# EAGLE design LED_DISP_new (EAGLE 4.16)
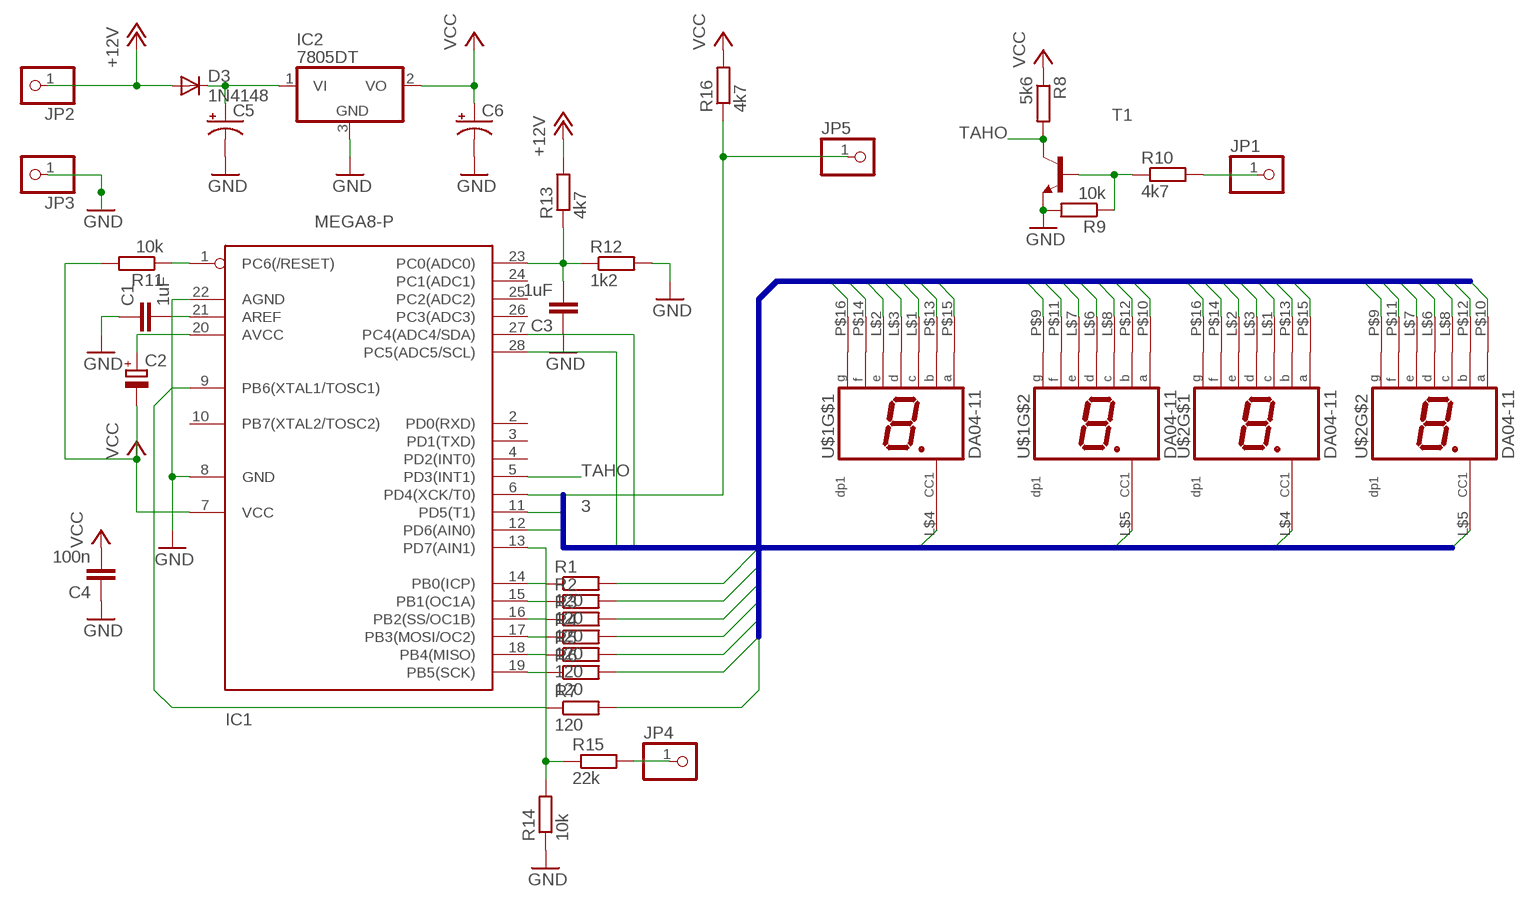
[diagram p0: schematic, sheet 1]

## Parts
C1  1uF  C-EUC1206  [C1206]
C2  CPOL-EUE2,5-6E  [E2,5-6E]
C3  1uF  C-EUC1206  [C1206]
C4  100n  C-EUC1206  [C1206]
C5  CPOL-USSANYO_C6  [SANYO-OSCON_C6]
C6  CPOL-USSANYO_C6  [SANYO-OSCON_C6]
D3  1N4148  [DO35-10]
IC1  MEGA8-P  [DIL28-3]
IC2  7805DT  [TO252]
JP1  PINHD-1X1  [1X01]
JP2  PINHD-1X1  [1X01]
JP3  PINHD-1X1  [1X01]
JP4  PINHD-1X1  [1X01]
JP5  PINHD-1X1  [1X01]
R1  120  R-EU_R1206  [R1206]
R2  120  R-EU_R1206  [R1206]
R3  120  R-EU_R1206  [R1206]
R4  120  R-EU_R1206  [R1206]
R5  120  R-EU_R1206  [R1206]
R6  120  R-EU_R1206  [R1206]
R7  120  R-EU_R1206  [R1206]
R8  5k6  R-EU_R1206  [R1206]
R9  10k  R-EU_R1206  [R1206]
R10  4k7  R-EU_R1206  [R1206]
R11  10k  R-EU_R1206  [R1206]
R12  1k2  R-EU_R1206  [R1206]
R13  4k7  R-EU_R1206  [R1206]
R14  10k  R-EU_R1206  [R1206]
R15  22k  R-EU_R1206  [R1206]
R16  4k7  R-EU_R1206  [R1206]
T1  -NPN-SOT23-EBC  [SOT23-EBC]
U$1  DA04-11  [DA04]
U$2  DA04-11  [DA04]

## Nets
1: IC1.28(PC5(ADC5/SCL)) U$2.L$5(CC)
2: IC1.27(PC4(ADC4/SDA)) U$2.L$4(CC)
3: IC1.11(PD5(T1)) U$1.L$5(CC)
4: IC1.12(PD6(AIN0)) U$1.L$4(CC)
+12V: D3.A JP2.1 R13.2
A: R1.2 U$1.P$10(A) U$1.P$15(A) U$2.P$10(A) U$2.P$15(A)
B: R2.2 U$1.P$12(B) U$1.P$13(B) U$2.P$12(B) U$2.P$13(B)
C: R3.2 U$1.L$1(C) U$1.L$8(C) U$2.L$1(C) U$2.L$8(C)
D: R4.2 U$1.L$3(D) U$1.L$6(D) U$2.L$3(D) U$2.L$6(D)
E: R5.2 U$1.L$2(E) U$1.L$7(E) U$2.L$2(E) U$2.L$7(E)
F: R6.2 U$1.P$11(F) U$1.P$14(F) U$2.P$11(F) U$2.P$14(F)
G: R7.2 U$1.P$9(G) U$1.P$16(G) U$2.P$9(G) U$2.P$16(G)
GND: C1.1 C3.1 C4.1 C5.- C6.- IC1.8(GND) IC1.22(AGND) IC2.3(GND) JP3.1 R9.2 R12.2 R14.1 T1.E
N$1: IC1.14(PB0(ICP)) R1.1
N$2: IC1.15(PB1(OC1A)) R2.1
N$3: IC1.16(PB2(SS/OC1B)) R3.1
N$4: IC1.17(PB3(MOSI/OC2)) R4.1
N$5: IC1.18(PB4(MISO)) R5.1
N$6: IC1.19(PB5(SCK)) R6.1
N$7: IC1.9(PB6(XTAL1/TOSC1)) R7.1
N$8: R9.1 R10.1 T1.B
N$9: JP1.1 R10.2
N$10: C1.2 IC1.21(AREF)
N$11: C2.+ IC1.20(AVCC)
N$13: IC1.1(PC6(/RESET)) R11.1
N$14: C3.2 IC1.23(PC0(ADC0)) R12.1 R13.1
N$15: C5.+ D3.C IC2.1(VI)
N$17: IC1.13(PD7(AIN1)) R14.2 R15.1
N$18: JP4.1 R15.2
N$19: IC1.6(PD4(XCK/T0)) JP5.1 R16.1
TAHO: IC1.5(PD3(INT1)) R8.2 T1.C
VCC: C2.- C4.2 C6.+ IC1.7(VCC) IC2.2(VO) R8.1 R11.2 R16.2
Unconnected: IC1.2(PD0(RXD)) IC1.3(PD1(TXD)) IC1.4(PD2(INT0)) IC1.10(PB7(XTAL2/TOSC2)) IC1.24(PC1(ADC1)) IC1.25(PC2(ADC2)) IC1.26(PC3(ADC3))

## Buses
A,B,C,D,E,F,G
1,2,3,4

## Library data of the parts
C1 C3 C4 = rcl:C-EU: CAPACITOR, European symbol
C2 = rcl:CPOL-EU: POLARIZED CAPACITOR, European symbol
C5 C6 = rcl:CPOL-US: POLARIZED CAPACITOR, American symbol
D3 = diode:1N4148: DIODE
IC1 = atmel:MEGA8-P: MICROCONTROLLER 8 Kbytes FLASH 1 kbytes SRAM 512 bytes EEPROM USART 4-channel 10 bit ADC 2-channel 8 bit ADC Source: avr.lbr
IC2 = linear:78*: Positive VOLTAGE REGULATOR Source: http://cache.national.com/ds/LM/LM78L05.pdf http://www.fairchildsemi.com/ds/LM/LM7805.pdf
JP1-JP5 = pinhead:PINHD-1X1: PIN HEADER
R1-R16 = rcl:R-EU_: RESISTOR, European symbol
T1 = transistor:*-NPN-: NPN Transistror
U$1 U$2 = display-kingbright:DA04-11

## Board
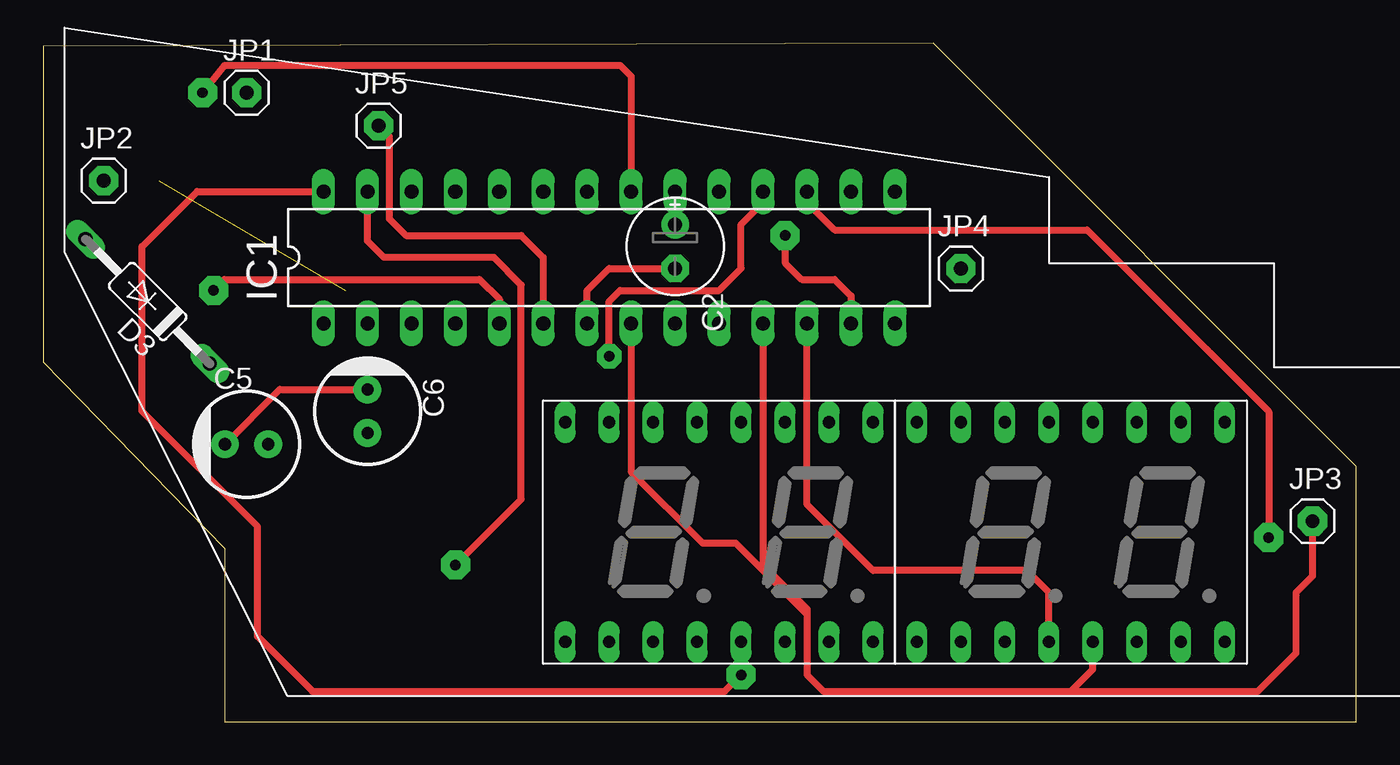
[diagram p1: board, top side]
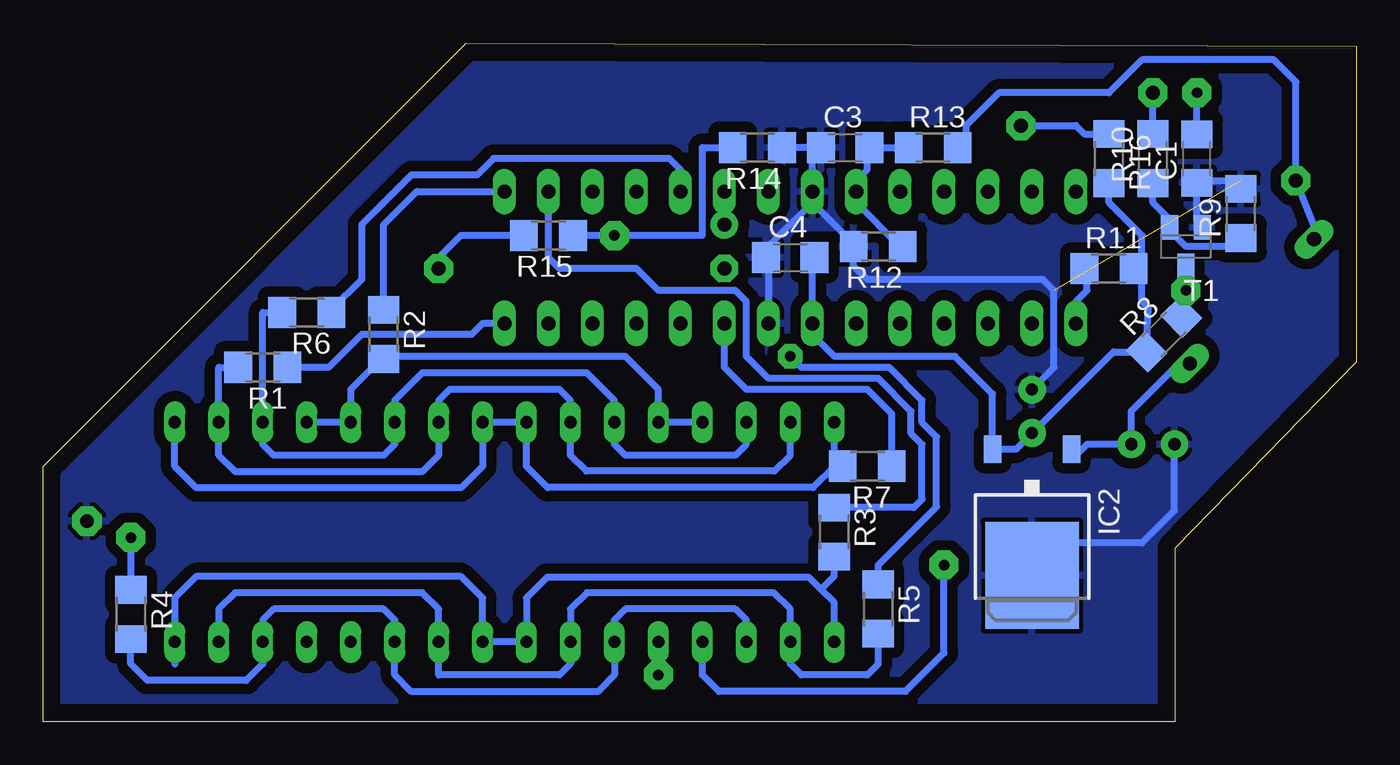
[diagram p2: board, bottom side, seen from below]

Size 75.87 x 39.2 mm. Coordinates in mm from the lower left corner, seen from the top.
Outline: 75.87,0 75.87,14.76 51.44,39.2 0,39.04 0,20.79 10.48,10 10.48,0 75.87,0
Copper layers (1*2): Top 0.035mm / dielectric 1.5mm / Route2 0.035mm
Design rules "default": minimum track width 10mil, minimum drill 24mil, track to track 8mil, track to pad 8mil, pad to pad 8mil, via to via 8mil, smd to smd 8mil, copper to edge 40mil, drill to drill 8mil, minimum pad ring 10mil, minimum via ring 8mil, stop-mask expansion 4mil, vias tented up to drill 0mil, thermal gap 10mil

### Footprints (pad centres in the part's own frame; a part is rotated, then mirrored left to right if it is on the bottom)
C1206 = smd 1.6 x 1.8: 1 -1.4,0; 2 1.4,0
E2,5-6E = drill 0.813 pad 1.6 round: + -1.27,0 | drill 0.813 pad 1.6 octagon: - 1.27,0
SANYO-OSCON_C6 = drill 0.7 pad 1.6 round: + 1.25,0; - -1.25,0
DO35-10 = drill 0.813 long: A 5.08,0; C -5.08,0
DIL28-3 = drill 0.813 long: 1 -16.51,-3.81; 2 -13.97,-3.81; 3 -11.43,-3.81; 4 -8.89,-3.81; 5 -6.35,-3.81; 6 -3.81,-3.81; 7 -1.27,-3.81; 8 1.27,-3.81; 9 3.81,-3.81; 10 6.35,-3.81; 11 8.89,-3.81; 12 11.43,-3.81; 13 13.97,-3.81; 14 16.51,-3.81; 15 16.51,3.81; 16 13.97,3.81; 17 11.43,3.81; 18 8.89,3.81; 19 6.35,3.81; 20 3.81,3.81; 21 1.27,3.81; 22 -1.27,3.81; 23 -3.81,3.81; 24 -6.35,3.81; 25 -8.89,3.81; 26 -11.43,3.81; 27 -13.97,3.81; 28 -16.51,3.81
TO252 = smd 1 x 1.6: 1 -2.28,-4.8; 2 2.28,-4.8 | smd 5.4 x 6.2: 3 0,2.5
1X01 = drill 0.8 pad 1.676 octagon: 1 0,0
R1206 = smd 1.6 x 1.803: 1 -1.422,0; 2 1.422,0
SOT23-EBC = smd 1 x 1.4: B 0.95,-1.1; C 0,1.1; E -0.95,-1.1
DA04 = drill 0.7 long: L$1 -8.89,-3.81; L$2 -6.35,-3.81; L$3 -3.81,-3.81; L$4 -1.27,-3.81; L$5 1.27,-3.81; L$6 3.81,-3.81; L$7 6.35,-3.81; L$8 8.89,-3.81; P$9 8.89,8.89; P$10 6.35,8.89; P$11 3.81,8.89; P$12 1.27,8.89; P$13 -1.27,8.89; P$14 -3.81,8.89; P$15 -6.35,8.89; P$16 -8.89,8.89

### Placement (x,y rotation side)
C1  9.21,32.54 90 bottom
C2  36.51,27.46 270 top
C3  29.53,33.17 0 bottom
C4  32.7,26.82 0 bottom
C5  11.75,16.03 0 top
C6  18.73,17.93 270 top
D3  6.03,24.28 135 top
IC1  32.7,26.82 0 top
IC2  18.73,10.95 180 bottom
JP1  11.75,36.35 0 top
JP2  3.49,31.27 0 top
JP3  73.34,11.58 0 top
JP4  53.02,26.19 0 top
JP5  19.37,34.44 0 top
R1  63.18,20.47 180 bottom
R2  56.2,22.38 270 bottom
R3  30.16,10.95 270 bottom
R4  70.8,6.19 270 bottom
R5  27.62,6.5 270 bottom
R6  60.64,23.65 180 bottom
R7  28.26,14.76 180 bottom
R8  11.11,22.38 45 bottom
R9  6.67,29.36 90 bottom
R10  11.75,32.54 90 bottom
R11  14.29,26.19 0 bottom
R12  27.62,27.46 180 bottom
R13  24.45,33.17 0 bottom
R14  34.61,33.17 180 bottom
R15  46.67,28.09 180 bottom
R16  14.29,32.54 270 bottom
T1  9.84,27.46 180 bottom
U$1  59.37,8.41 0 top
U$2  39.05,8.41 0 top

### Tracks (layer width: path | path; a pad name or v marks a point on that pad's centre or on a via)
1  (via drill 0.6 pad 1.68)
  Top 0.406: IC1.28 8.89,30.63 5.72,27.46 5.72,17.93 12.38,11.27 12.38,4.92 15.56,1.74 39.37,1.74 v40.32,2.69
  Bottom 0.406: v40.32,2.69 U$2.L$5
2  (via drill 0.6 pad 1.68)
  Top 0.406: IC1.27 18.73,27.78 19.69,26.82 26.03,26.82 27.62,25.24 27.62,12.85 v23.81,9.04
  Bottom 0.406: U$2.L$4 37.78,2.69 36.83,1.74 26.04,1.74 23.81,3.96 v23.81,9.04
3
  Top 0.406: IC1.11 41.59,9.04 44.13,6.5 44.13,2.69 45.09,1.74 59.37,1.74 60.64,3.01 U$1.L$5
4
  Top 0.406: U$1.L$4 58.1,7.45 56.83,8.73 47.94,8.73 44.13,12.53 IC1.12
+12V
  Bottom 0.406: R13.2 23.18,33.17 22.54,33.81 22.54,34.44 20.64,36.35 14.29,36.35 12.38,38.25 4.76,38.25 3.49,36.98 JP2.1 2.22,28.09 D3.A
A
  Bottom 0.406: U$2.P$15 32.7,15.39 33.62,14.47 44.48,14.47 45.4,15.39 U$2.P$10 45.4,18.57 46.04,19.2 52.39,19.2 53.02,18.57 U$1.P$15 53.02,15.39 53.98,14.43 64.76,14.43 65.72,15.39 U$1.P$10 65.72,20.47 R1.2
B
  Bottom 0.406: U$1.P$12 U$1.P$13 58.1,19.2 56.83,20.47 56.83,21.11 | U$2.P$13 U$2.P$12 40.32,19.2 42.23,21.11 56.83,21.11 | 56.83,21.11 R2.2
C
  Bottom 0.406: 68.26,3.33 U$1.L$8 68.26,7.14 67.02,8.38 51.73,8.38 50.48,7.14 U$1.L$1 U$2.L$8 47.94,7.14 46.74,8.34 31.62,8.34 30.93,7.64 | U$2.L$1 30.16,6.87 30.93,7.64 | R3.2 30.16,8.41 30.93,7.64
D
  Bottom 0.406: 63.18,4.92 63.18,5.87 62.55,6.5 56.2,6.5 55.56,5.87 U$1.L$3 55.56,2.69 54.6,1.73 43.82,1.73 42.86,2.69 U$2.L$6 42.86,5.87 42.23,6.5 35.88,6.5 35.24,5.87 U$2.L$3 | R4.2 70.8,3.33 69.85,2.38 64.14,2.38 63.18,3.33 63.18,4.92 | 63.18,4.92 U$1.L$6
E
  Bottom 0.406: U$1.L$7 65.72,6.5 64.78,7.45 53.97,7.45 53.02,6.5 U$1.L$2 53.02,2.69 46.04,2.69 45.4,3.33 U$2.L$7 45.4,6.5 44.46,7.45 33.65,7.45 32.7,6.5 U$2.L$2 32.7,3.33 32.07,2.69 28.26,2.69 27.62,3.33 R5.2
F
  Bottom 0.406: U$2.P$14 35.24,16.03 35.88,15.39 42.23,15.39 42.86,16.03 U$2.P$11 42.86,18.57 44.45,20.16 53.97,20.16 55.56,18.57 U$1.P$14 55.56,16.03 56.2,15.39 62.55,15.39 63.18,16.03 U$1.P$11 63.18,23.65 R6.2 61.91,23.65
G
  Bottom 0.406: U$1.P$9 68.26,14.76 67.02,13.51 51.73,13.51 50.48,14.76 U$1.P$16 U$2.P$9 47.94,14.76 46.72,13.53 31.39,13.53 30.16,14.76 | 30.16,14.76 U$2.P$16 | 29.53,14.76 R7.2 30.16,14.76
GND  (1 unrouted)
  Top 0.406: C6.- 18.73,19.2 13.67,19.2 C5.- | JP3.1 73.34,8.41 72.39,7.45 72.39,3.96 70.17,1.74 45.09,1.74 44.13,2.69 44.13,6.19 40.01,10.31 38.1,10.31 33.97,14.44 IC1.8
  Bottom 0.406: IC1.8 33.97,26.82 C4.1 34.1,27.33 31.43,30 | 31.43,30 IC1.22 31.43,32.54 30.8,33.17 C3.1 R14.1 | C5.- 10.5,12.2 12.38,10.31 16.83,10.31 18.73,8.41 IC2.3 | C6.- 18.73,19.2 17.46,20.47 17.46,24.92 18.1,25.55 28.26,25.55 29.04,26.34 R12.2 28.89,27.46 31.43,30 | 9.21,31.27 C1.1 9.21,28.87 | T1.E 9.21,28.87 | R9.2 6.67,30.63 7.3,31.27 9.21,31.27 | 9.21,28.87 9.21,31.27 | 9.21,31.27 6.67,31.27
  pour Bottom (isolate 0.61): -1.59,42.7 62.55,42.7 91.76,13.49 91.76,-2.39 6.67,-2.39 6.67,9.04 0.95,9.04 0.95,22.38 -4.76,22.38 -4.76,42.06 -2.86,42.06
N$1
  Bottom 0.406: R1.1 59.37,20.47 57.47,22.38 51.12,22.38 50.48,23.01 IC1.14
N$2
  Bottom 0.406: R2.1 56.2,28.73 54.29,30.63 IC1.15
N$3
  Bottom 0.406: R3.1 25.57,12.37 25.08,12.85 25.08,16.03 25.72,16.66 25.72,17.93 27.62,19.84 33.97,19.84 35.24,21.11 35.24,24.28 35.88,24.92 40.32,24.92 41.59,26.19 46.04,26.19 46.67,26.82 IC1.16
N$4  (via drill 0.6 pad 1.68)
  Top 0.406: IC1.17 44.13,30 45.72,28.41 60.33,28.41 70.8,17.93 v70.8,10.63
  Bottom 0.406: 70.8,7.45 R4.1 v70.8,10.63
N$5  (via drill 0.6 pad 1.42)
  Top 0.406: v32.7,21.11 32.7,24.28 33.34,24.92 39.05,24.92 40.32,26.19 40.32,28.73 41.59,30 IC1.18
  Bottom 0.406: R5.1 27.62,9.04 24.25,12.42 24.25,16.46 25.08,17.3 25.08,18.57 26.99,20.47 32.07,20.47 v32.7,21.11
N$6
  Bottom 0.406: R6.1 59.22,23.8 57.47,25.55 57.47,28.73 54.61,31.58 50.8,31.58 49.85,32.54 39.69,32.54 39.05,31.9 IC1.19
N$7
  Bottom 0.406: R7.1 26.84,17.78 28.26,19.2 35.24,19.2 36.51,20.47 IC1.9
N$8
  Bottom 0.406: 11.75,31.27 R10.1 11.75,30 10.79,29.04 T1.B 10.79,28.41 9.84,27.46 7.3,27.46 6.67,28.09 R9.1
N$9
  Bottom 0.406: R10.2 JP1.1
N$10  (via drill 0.6 pad 1.68)
  Top 0.406: IC1.21 33.97,37.3 33.34,37.94 10.48,37.94 v9.21,36.35
  Bottom 0.406: 9.21,33.81 C1.2 v9.21,36.35
N$11
  Bottom 0.406: C2.+ IC1.20
N$13
  Bottom 0.406: IC1.1 16.19,24.28 15.56,24.92 15.56,26.19 R11.1
N$14
  Bottom 0.406: 25.72,33.17 R13.1 C3.2 28.26,33.17 28.26,31.9 28.89,31.27 IC1.23 28.89,30 26.35,27.46 R12.1
N$15
  Bottom 0.406: D3.C 10.48,20.47 13.02,17.93 13.02,16.03 C5.+ 15.56,16.03 16.19,15.39 16.45,15.65 IC2.1
N$17  (via drill 0.6 pad 1.68)
  Top 0.406: IC1.13 46.67,24.6 45.72,25.55 43.81,25.55 42.86,26.5 v42.86,28.09
  Bottom 0.406: R15.1 v42.86,28.09 37.78,28.09 37.78,33.17 R14.2
N$18
  Bottom 0.406: R15.2 51.75,28.09 53.02,26.82 JP4.1
N$19
  Top 0.406: IC1.6 28.89,26.82 27.62,28.09 20.95,28.09 20,29.05 20,33.81 JP5.1
  Bottom 0.406: R16.1 15.71,33.96 16.19,34.44 JP5.1
TAHO  (via drill 0.6 pad 1.68)
  Top 0.406: IC1.5 26.35,24.41 25.21,25.55 10.48,25.55 v9.84,24.92
  Bottom 0.406: R8.2 9.84,23.65 v9.84,24.92 9.84,25.55 T1.C
VCC
  Top 0.406: C2.- 32.7,26.19 31.43,24.92 IC1.7
  Bottom 0.406: C4.2 31.43,26.82 IC1.7 31.43,22.38 30.16,21.11 23.18,21.11 21.01,18.94 IC2.2 19.65,15.75 18.73,16.66 | 13.02,26.19 12.38,25.55 12.38,24.28 12.01,23.91 R8.1 14.02,21.37 18.73,16.66 | 18.73,16.66 C6.+ | R16.2 14.29,30 12.38,28.09 12.38,26.82 13.02,26.19 | 13.02,26.19 R11.2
